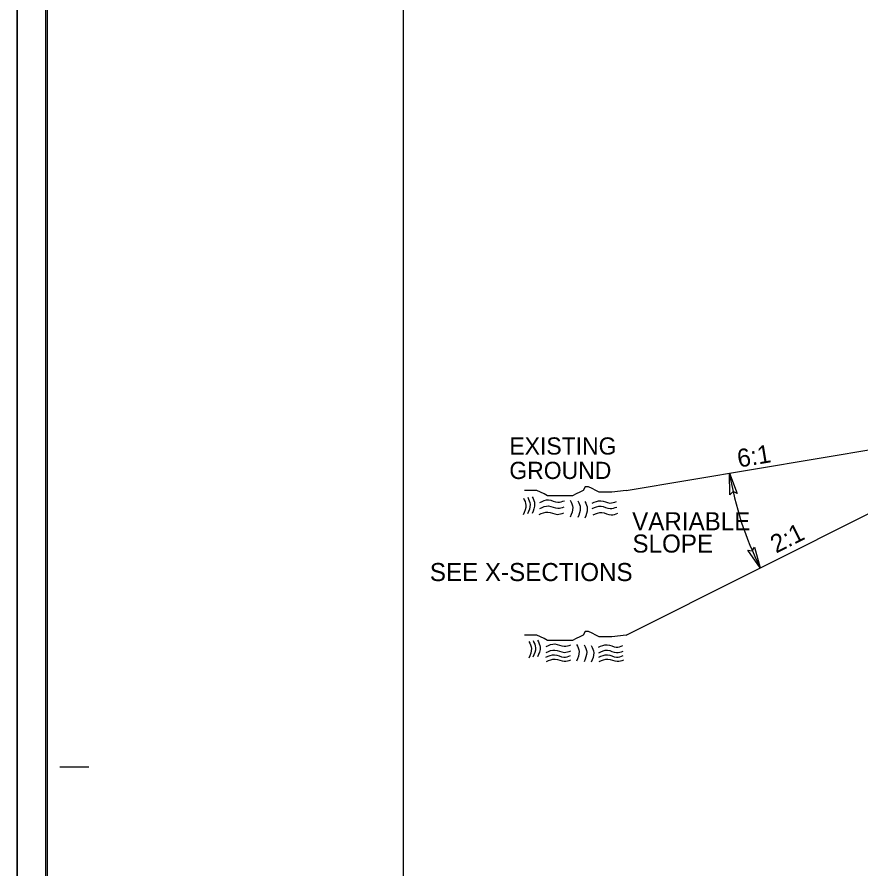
# Model space of a CAD drawing. Extents: x 2294342 to 2294901, y 719427 to 719941.
# Drawn here: x 2294454.5 to 2294527.5, y 719757.8 to 719831.5 of the extents above; entities that cross this region are included whole.
import ezdxf

# ---------------------------------------------------------------- set-up
doc = ezdxf.new("R2010")
doc.units = 0
for name, color, linetype in [('Default', 7, 'Continuous'), ('Old_Level_1', 7, 'Continuous'), ('Old_Level_11', 7, 'Continuous'), ('Old_Level_2', 7, 'Continuous'), ('Sheet Plot Border Inside CELL', 7, 'Continuous'), ('Sheet Plot Border Outside CELL', 7, 'Continuous'), ('Sheet Typical CELL', 7, 'Continuous'), ('Typical Hinge Slope Arterial CELL', 7, 'Continuous')]:
    doc.layers.add(name, color=color, linetype=linetype)

msp = doc.modelspace()

# ---------------------------------------------------------------- linework, layer by layer
at = {"layer": 'Default'}
msp.add_lwpolyline([(2294454.524, 719936.169), (2294794.524, 719936.169), (2294794.524, 719716.169), (2294454.524, 719716.169)], close=True, dxfattribs=at)
msp.add_lwpolyline([(2294454.524, 719936.169), (2294794.524, 719936.169), (2294794.524, 719716.169), (2294454.524, 719716.169)], close=True, dxfattribs=at)
at = {"layer": 'Old_Level_11'}
for points in [[(2294516.161, 719790.168), (2294516.123, 719792.036), (2294516.796, 719790.28), (2294516.429, 719790.449)], [(2294518.288, 719785.651), (2294518.785, 719783.85), (2294517.701, 719785.386), (2294518.097, 719785.312)]]:
    msp.add_lwpolyline(points, close=True, dxfattribs=at)
at = {"layer": 'Old_Level_2'}
for points in [[(2294498.312, 719789.885), (2294498.523, 719789.266), (2294498.295, 719788.442)], [(2294498.312, 719789.885), (2294498.523, 719789.266), (2294498.295, 719788.442)], [(2294498.677, 719789.957), (2294498.886, 719789.335), (2294498.658, 719788.51)], [(2294498.677, 719789.957), (2294498.886, 719789.335), (2294498.658, 719788.51)], [(2294499.066, 719789.997), (2294499.279, 719789.375), (2294499.051, 719788.554)], [(2294499.066, 719789.997), (2294499.279, 719789.375), (2294499.051, 719788.554)], [(2294499.731, 719789.513), (2294500.48, 719789.729), (2294501.278, 719789.527), (2294501.848, 719789.656)], [(2294499.731, 719789.513), (2294500.48, 719789.729), (2294501.278, 719789.527), (2294501.848, 719789.656)], [(2294502.36, 719789.69), (2294502.569, 719789.07), (2294502.345, 719788.247)], [(2294502.36, 719789.69), (2294502.569, 719789.07), (2294502.345, 719788.247)], [(2294503.015, 719789.64), (2294503.227, 719789.018), (2294503, 719788.194)], [(2294503.015, 719789.64), (2294503.227, 719789.018), (2294503, 719788.194)], [(2294503.622, 719789.585), (2294503.833, 719788.963), (2294503.605, 719788.142)], [(2294503.622, 719789.585), (2294503.833, 719788.963), (2294503.605, 719788.142)], [(2294504.244, 719789.442), (2294504.997, 719789.657), (2294505.789, 719789.454), (2294506.363, 719789.581)], [(2294504.244, 719789.442), (2294504.997, 719789.657), (2294505.789, 719789.454), (2294506.363, 719789.581)], [(2294499.668, 719788.462), (2294500.42, 719788.674), (2294501.218, 719788.476), (2294501.79, 719788.603)], [(2294499.668, 719788.462), (2294500.42, 719788.674), (2294501.218, 719788.476), (2294501.79, 719788.603)], [(2294499.726, 719788.99), (2294500.48, 719789.203), (2294501.271, 719789), (2294501.843, 719789.129)], [(2294499.726, 719788.99), (2294500.48, 719789.203), (2294501.271, 719789), (2294501.843, 719789.129)], [(2294504.264, 719788.97), (2294505.017, 719789.187), (2294505.809, 719788.982), (2294506.383, 719789.111)], [(2294504.264, 719788.97), (2294505.017, 719789.187), (2294505.809, 719788.982), (2294506.383, 719789.111)], [(2294504.34, 719788.425), (2294505.092, 719788.639), (2294505.887, 719788.436), (2294506.46, 719788.566)], [(2294504.34, 719788.425), (2294505.092, 719788.639), (2294505.887, 719788.436), (2294506.46, 719788.566)], [(2294499.539, 719777.611), (2294499.753, 719776.989), (2294499.524, 719776.167)], [(2294499.539, 719777.611), (2294499.753, 719776.989), (2294499.524, 719776.167)], [(2294498.785, 719777.499), (2294498.997, 719776.879), (2294498.768, 719776.055)], [(2294498.785, 719777.499), (2294498.997, 719776.879), (2294498.768, 719776.055)], [(2294499.15, 719777.57), (2294499.36, 719776.948), (2294499.131, 719776.124)], [(2294499.15, 719777.57), (2294499.36, 719776.948), (2294499.131, 719776.124)], [(2294500.282, 719777.062), (2294501.032, 719777.279), (2294501.83, 719777.076), (2294502.4, 719777.205)], [(2294500.282, 719777.062), (2294501.032, 719777.279), (2294501.83, 719777.076), (2294502.4, 719777.205)], [(2294502.911, 719777.24), (2294503.12, 719776.62), (2294502.896, 719775.796)], [(2294502.911, 719777.24), (2294503.12, 719776.62), (2294502.896, 719775.796)], [(2294503.567, 719777.19), (2294503.778, 719776.568), (2294503.552, 719775.744)], [(2294503.567, 719777.19), (2294503.778, 719776.568), (2294503.552, 719775.744)], [(2294504.174, 719777.135), (2294504.385, 719776.513), (2294504.157, 719775.691)], [(2294504.174, 719777.135), (2294504.385, 719776.513), (2294504.157, 719775.691)], [(2294504.795, 719776.992), (2294505.549, 719777.206), (2294506.341, 719777.003), (2294506.915, 719777.13)], [(2294504.795, 719776.992), (2294505.549, 719777.206), (2294506.341, 719777.003), (2294506.915, 719777.13)], [(2294500.253, 719776.124), (2294501.005, 719776.339), (2294501.801, 719776.136), (2294502.373, 719776.265)], [(2294500.253, 719776.124), (2294501.005, 719776.339), (2294501.801, 719776.136), (2294502.373, 719776.265)], [(2294500.278, 719776.54), (2294501.031, 719776.753), (2294501.823, 719776.549), (2294502.395, 719776.679)], [(2294500.278, 719776.54), (2294501.031, 719776.753), (2294501.823, 719776.549), (2294502.395, 719776.679)], [(2294504.815, 719776.52), (2294505.569, 719776.737), (2294506.36, 719776.531), (2294506.935, 719776.66)], [(2294504.815, 719776.52), (2294505.569, 719776.737), (2294506.36, 719776.531), (2294506.935, 719776.66)], [(2294504.816, 719776.124), (2294505.568, 719776.339), (2294506.364, 719776.136), (2294506.936, 719776.265)], [(2294504.816, 719776.124), (2294505.568, 719776.339), (2294506.364, 719776.136), (2294506.936, 719776.265)], [(2294500.294, 719775.762), (2294501.046, 719775.974), (2294501.844, 719775.776), (2294502.416, 719775.903)], [(2294504.857, 719775.762), (2294505.609, 719775.974), (2294506.406, 719775.776), (2294506.979, 719775.903)]]:
    msp.add_spline(points, degree=3, dxfattribs=at)
at = {"layer": 'Sheet Plot Border Inside CELL'}
msp.add_lwpolyline([(2294790.424, 719931.679), (2294457.124, 719931.679), (2294457.124, 719720.659), (2294790.424, 719720.659)], close=True, dxfattribs=at)
at = {"layer": 'Sheet Plot Border Outside CELL'}
for points in [[(2294793.79, 719941.133), (2294456.99, 719941.133), (2294456.99, 719721.133), (2294793.79, 719721.133)], [(2294794.524, 719936.169), (2294454.524, 719936.169), (2294454.524, 719716.169), (2294794.524, 719716.169)]]:
    msp.add_lwpolyline(points, close=True, dxfattribs=at)
at = {"layer": 'Sheet Typical CELL'}
msp.add_line((2294458.224, 719766.669), (2294460.724, 719766.669), dxfattribs=at)
msp.add_lwpolyline([(2294787.924, 719931.169), (2294487.924, 719931.169), (2294487.924, 719721.169), (2294787.924, 719721.169)], close=True, dxfattribs=at)
at = {"layer": 'Typical Hinge Slope Arterial CELL'}
for p, q in [((2294507.179, 719778.047), (2294544.673, 719796.794)), ((2294507.179, 719790.545), (2294529.675, 719794.294))]:
    msp.add_line(p, q, dxfattribs=at)
for points in [[(2294507.179, 719790.545), (2294505.947, 719790.392), (2294505.639, 719790.392), (2294505.177, 719790.392), (2294504.869, 719790.392), (2294504.561, 719790.545), (2294504.253, 719790.7), (2294503.945, 719790.854), (2294503.637, 719790.854), (2294503.482, 719790.545), (2294503.174, 719790.392), (2294502.866, 719790.237), (2294502.558, 719790.084), (2294502.25, 719790.084), (2294501.942, 719790.084), (2294501.634, 719790.084), (2294501.326, 719790.084), (2294501.018, 719790.084), (2294500.71, 719790.084), (2294500.403, 719790.084), (2294500.095, 719790.237), (2294499.787, 719790.392), (2294499.479, 719790.545), (2294499.016, 719790.545), (2294498.708, 719790.545), (2294498.4, 719790.545)], [(2294507.179, 719778.047), (2294505.947, 719777.894), (2294505.639, 719777.894), (2294505.177, 719777.894), (2294504.869, 719777.894), (2294504.561, 719778.047), (2294504.253, 719778.202), (2294503.945, 719778.356), (2294503.637, 719778.356), (2294503.482, 719778.047), (2294503.174, 719777.894), (2294502.866, 719777.739), (2294502.558, 719777.586), (2294502.25, 719777.586), (2294501.942, 719777.586), (2294501.634, 719777.586), (2294501.326, 719777.586), (2294501.018, 719777.586), (2294500.71, 719777.586), (2294500.403, 719777.586), (2294500.095, 719777.739), (2294499.787, 719777.894), (2294499.479, 719778.047), (2294499.016, 719778.047), (2294498.708, 719778.047), (2294498.4, 719778.047)]]:
    msp.add_lwpolyline(points, dxfattribs=at)
msp.add_arc((2294544.673, 719796.794), 28.944, 189.46245, 206.56505, dxfattribs=at)

# ---------------------------------------------------------------- texts
at = {"layer": 'Old_Level_1'}
for s, height, rotation, p in [('EXISTING', 1.4844, 359.99996, (2294497.09, 719793.645)), ('6:1', 1.5625, 9.46232, (2294516.929, 719792.515)), ('GROUND', 1.4844, 359.99996, (2294497.09, 719791.535)), ('2:1', 1.5625, 26.56505, (2294520.158, 719785.08)), ('SEE X-SECTIONS', 1.5625, 359.99996, (2294490.217, 719782.71))]:
    msp.add_text(s, height=height, rotation=rotation, dxfattribs=at).set_placement(p)
at = {"layer": 'Typical Hinge Slope Arterial CELL'}
for s, p in [('VARIABLE ', (2294507.709, 719787.101)), ('SLOPE', (2294507.736, 719785.173))]:
    msp.add_text(s, height=1.5625, dxfattribs=at).set_placement(p)

doc.saveas('drawing.dxf')
